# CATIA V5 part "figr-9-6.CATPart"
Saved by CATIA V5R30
Part number: Part2
Bounding box of the stored display mesh (mm): x -75 to 75, y -75 to 96.278, z -26.878 to 0
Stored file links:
  D:\PROJECTS\CATIA V56R 2020\Resources\Parts File\c09_catia_v5_6r2020_prt\figr-9-6.CATPart
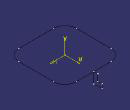
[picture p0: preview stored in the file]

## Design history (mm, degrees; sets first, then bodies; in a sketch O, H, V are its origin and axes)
Body1 (main body)
  Sketch1 on xy-plane, origin (0, 0, 0), H (1, 0, 0), V (0, 1, 0)
    point P1 (-75, 75)
    line L1 (-45, 75) -> (45, 75)
    line L2 (75, 45) -> (75, -45)
    line L3 (45, -75) -> (-45, -75)
    line L4 (-75, -45) -> (-75, 45)
    point P2 (75, 75)
    point P3 (75, -75)
    point P4 (-75, -75)
    axis line L5 (75, -75) -> (-75, 75)
    arc A1 centre (45, -45) radius 30 from (75, -45) to (45, -75) cw
    arc A2 centre (45, 45) radius 30 from (45, 75) to (75, 45) cw
    arc A3 centre (-45, 45) radius 30 from (-45, 75) to (-75, 45) ccw
    arc A4 centre (-45, -45) radius 30 from (-45, -75) to (-75, -45) cw
    distance P2 P3 = 150
    distance P3 P4 = 150
    radius A1 = 30
    radius A2 = 30
    radius A3 = 30
    radius A4 = 30
    horizontal: L1 H, L3 H
    vertical: L2 V, L4 V
    midpoint: O L5
    coincidence: L2 P3, L3 P3, L1 P2, L2 P2, L1 P1, L4 P1, L3 P4, L4 P4
    tangency: A1 L2, A1 L3, A2 L1, A2 L2, A3 L1, A3 L4, A4 L3, A4 L4
  Sketch2 on yz-plane, origin (0, 0, 0), H (0, 1, 0), V (0, 0, 1)
    point P1 (85, 0)
    line L1 (85, 0) -> (85, -16.8782)
    line L2 (85, -16.8782) -> (96.2781, -16.8782)
    line L3 (96.2781, -16.8782) -> (96.2781, -26.8782)
    line L4 (96.2781, -26.8782) -> (75, -26.8782)
    line L5 (75, -26.8782) -> (75, 0)
    point P6 (75, 0)
    line L6 (75, 0) -> (85, 0)
    reference projected point E1 (75, 0) from edge of Sketch1
    length L3 = 10
    length L6 = 10
    coincidence: P1 H, P6 H, P6 E1
    vertical: L1 V, L3 V, L5 V
    horizontal: L2 H, L4 H, L6 H
  Rib1: profile Sketch2, centre curve Sketch1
